(* Logix 5000 project; controller AMCI_3202_AOP_AOI_sample_RSLogix_V28 vendor 1 type 14 code 92 rev 28.11; software revision 28.00 *)

TASK MainTask (continuous, watchdog 500 ms) : MainProgram

MODULES
   Local : vendor 1 type 14 code 92 (ICP 0, rev 28.11)
      AMCI_3202 : vendor 10 type 100 code 32 (ICP 3, rev 1.1, Output RPI 5 ms)
      EN2TR : vendor 1 type 12 code 200 (ICP 2, Ethernet 192.168.0.5, rev 10.1)
END_MODULES

ADD_ON_INSTRUCTION AMCI_3202_AOP_Absolute_Move   (* revision 1.0, vendor AMCI, ExecuteEnableInFalse *)
VAR_INPUT
   axis_status_bits : INT; {required}
   channel_number : INT; {required}
   _0_normal_1_S_Curve_Acceleration : BOOL;
   _0_Triangular_1_Trapezoidal_S_Curve : BOOL;
   _0_Target_Position_1_Encoder_Move : BOOL;
   Target_Position : DINT; {required}
   Programmed_speed : DINT; {required}
   Acceleration : DINT; {required}
   Deceleration : DINT; {required}
END_VAR
VAR_IN_OUT
   AMCI_3202_output_data : AM:1756_3202:O:0; {required}
END_VAR
VAR_OUTPUT
   EN : BOOL; {access Read Only, visible}
   ER : BOOL; {access Read Only, visible}
END_VAR
VAR
   command_data_block : DINT[8]; {access None}
END_VAR

ROUTINE EnableInFalse   (* ladder *)
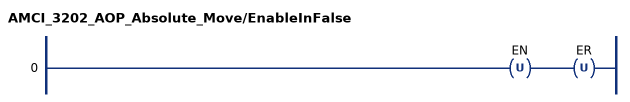
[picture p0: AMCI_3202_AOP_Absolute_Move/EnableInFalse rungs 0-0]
   0: OTU(EN)OTU(ER);
END_ROUTINE

ROUTINE Logic   (* ladder *)
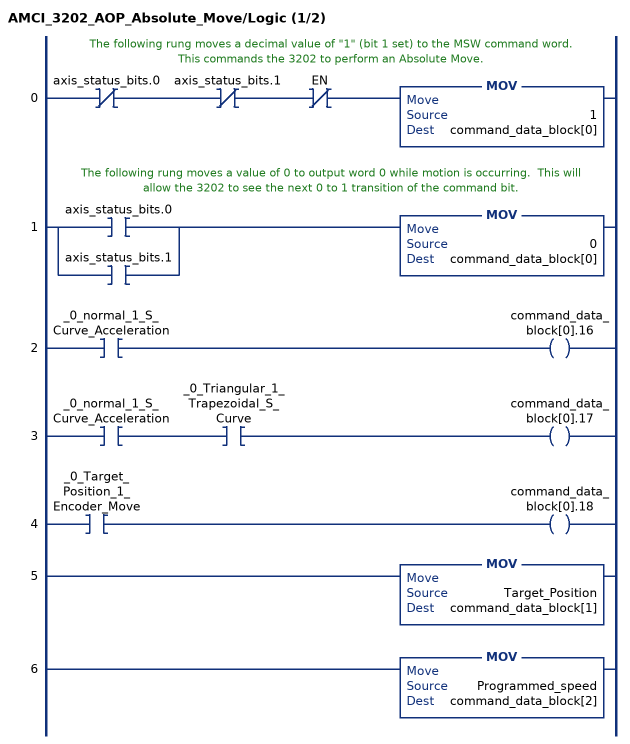
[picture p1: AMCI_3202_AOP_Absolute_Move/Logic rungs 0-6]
   // The following rung moves a decimal value of "1" (bit 1 set) to the MSW command word.  This commands the 3202 to perform an Absolute Move.
   0: XIO(axis_status_bits.0)XIO(axis_status_bits.1)XIO(EN)MOV(1,command_data_block[0]);
   // The following rung moves a value of 0 to output word 0 while motion is occurring.  This will allow the 3202 to see the next 0 to 1 transition of the command bit.
   1: [XIC(axis_status_bits.0) ,XIC(axis_status_bits.1) ]MOV(0,command_data_block[0]);
   2: XIC(_0_normal_1_S_Curve_Acceleration)OTE(command_data_block[0].16);
   3: XIC(_0_normal_1_S_Curve_Acceleration)XIC(_0_Triangular_1_Trapezoidal_S_Curve)OTE(command_data_block[0].17);
   4: XIC(_0_Target_Position_1_Encoder_Move)OTE(command_data_block[0].18);
   5: MOV(Target_Position,command_data_block[1]);
   6: MOV(Programmed_speed,command_data_block[2]);
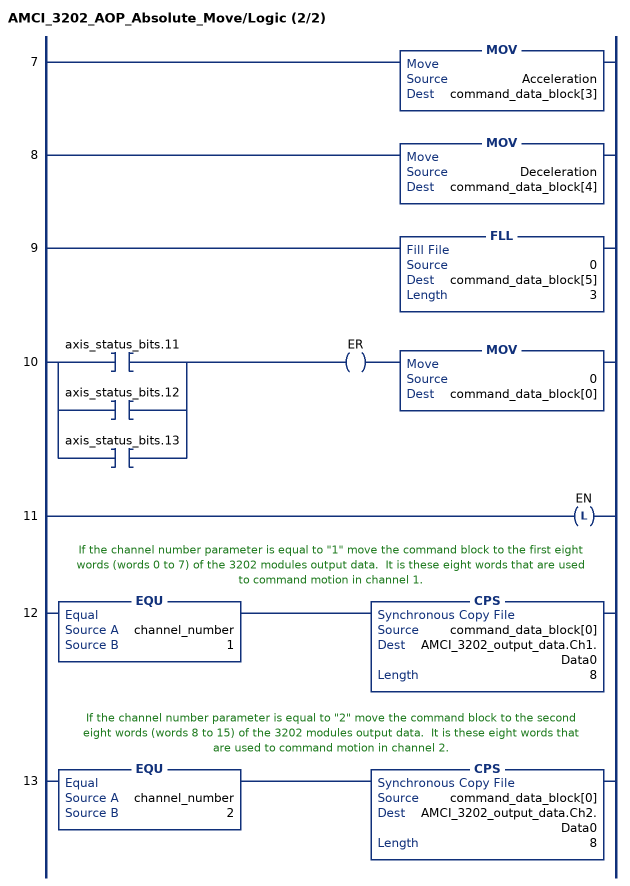
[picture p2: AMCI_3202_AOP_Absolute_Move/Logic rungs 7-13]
   7: MOV(Acceleration,command_data_block[3]);
   8: MOV(Deceleration,command_data_block[4]);
   9: FLL(0,command_data_block[5],3);
   10: [XIC(axis_status_bits.11) ,XIC(axis_status_bits.12) ,XIC(axis_status_bits.13) ]OTE(ER)MOV(0,command_data_block[0]);
   11: OTL(EN);
   // If the channel number parameter is equal to "1" move the command block to the first eight words (words 0 to 7) of the 3202 modules output data.  It is these eight words that are used to command motion in channel 1.
   12: EQU(channel_number,1)CPS(command_data_block[0],AMCI_3202_output_data.Ch1.Data0,8);
   // If the channel number parameter is equal to "2" move the command block to the second eight words (words 8 to 15) of the 3202 modules output data.  It is these eight words that are used to command motion in channel 2.
   13: EQU(channel_number,2)CPS(command_data_block[0],AMCI_3202_output_data.Ch2.Data0,8);
END_ROUTINE
END_ADD_ON_INSTRUCTION

ADD_ON_INSTRUCTION AMCI_3202_AOP_Configure   (* revision 1.0 *)
VAR_INPUT
   channel_number : INT; {required}
   capture_input : BOOL; {required}
   capture_input_active_state : BOOL; {required}
   external_input : BOOL; {required}
   external_input_active_state : BOOL; {required}
   home_input : BOOL; {required}
   home_input_active_state : BOOL; {required}
   Emergency_Stop : BOOL; {required}
   Emergency_Stop_active_state : BOOL; {required}
   CW_Limit : BOOL; {required}
   CW_Limit_actitve_state : BOOL; {required}
   CCW_Limit : BOOL; {required}
   CCW_Limit_active_state : BOOL; {required}
   Backplane_Home_Proximity_Enable : BOOL;
   Quad_Encoder : BOOL; {required}
   Diagnostic_Feedback : BOOL;
   _0_CW_CCW_1_step_direction : BOOL; {required}
   _0_enable_1_disable_channel : BOOL;
   Starting_Speed : DINT; {required}
   _0_limit_home_1_marker_pulse_home : BOOL;
END_VAR
VAR_IN_OUT
   AMCI_3202_output_data : AM:1756_3202:O:0; {required}
END_VAR
VAR
   command_data_block : DINT[8];
        [0].31   // Mode Bit 1=Configuraiton Mode 0=Command Mode
END_VAR

ROUTINE Logic   (* ladder *)
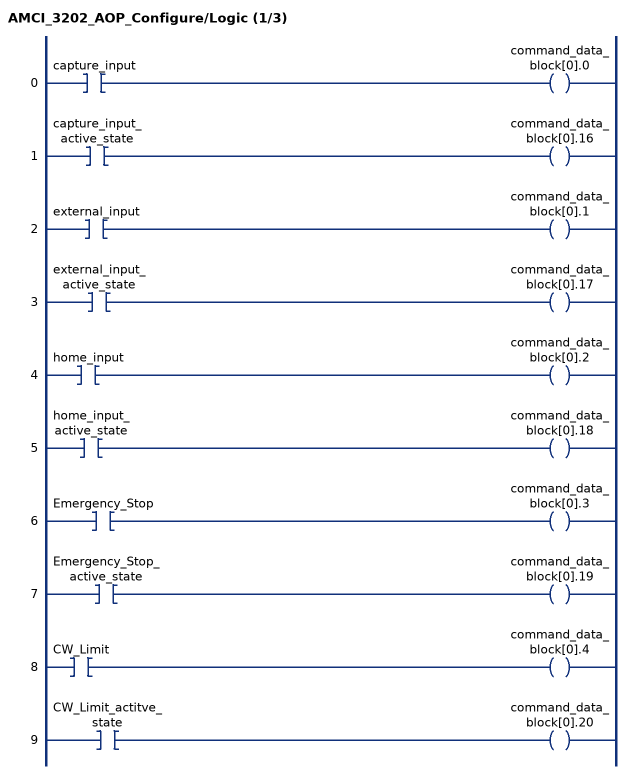
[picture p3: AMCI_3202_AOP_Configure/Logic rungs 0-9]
   0: XIC(capture_input)OTE(command_data_block[0].0);
   1: XIC(capture_input_active_state)OTE(command_data_block[0].16);
   2: XIC(external_input)OTE(command_data_block[0].1);
   3: XIC(external_input_active_state)OTE(command_data_block[0].17);
   4: XIC(home_input)OTE(command_data_block[0].2);
   5: XIC(home_input_active_state)OTE(command_data_block[0].18);
   6: XIC(Emergency_Stop)OTE(command_data_block[0].3);
   7: XIC(Emergency_Stop_active_state)OTE(command_data_block[0].19);
   8: XIC(CW_Limit)OTE(command_data_block[0].4);
   9: XIC(CW_Limit_actitve_state)OTE(command_data_block[0].20);
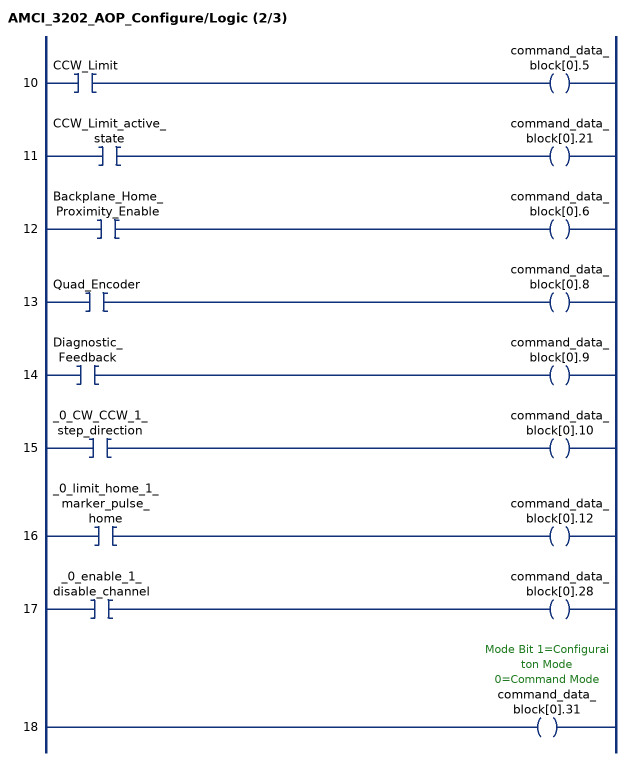
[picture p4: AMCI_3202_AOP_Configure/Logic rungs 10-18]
   10: XIC(CCW_Limit)OTE(command_data_block[0].5);
   11: XIC(CCW_Limit_active_state)OTE(command_data_block[0].21);
   12: XIC(Backplane_Home_Proximity_Enable)OTE(command_data_block[0].6);
   13: XIC(Quad_Encoder)OTE(command_data_block[0].8);
   14: XIC(Diagnostic_Feedback)OTE(command_data_block[0].9);
   15: XIC(_0_CW_CCW_1_step_direction)OTE(command_data_block[0].10);
   16: XIC(_0_limit_home_1_marker_pulse_home)OTE(command_data_block[0].12);
   17: XIC(_0_enable_1_disable_channel)OTE(command_data_block[0].28);
   18: OTE(command_data_block[0].31);
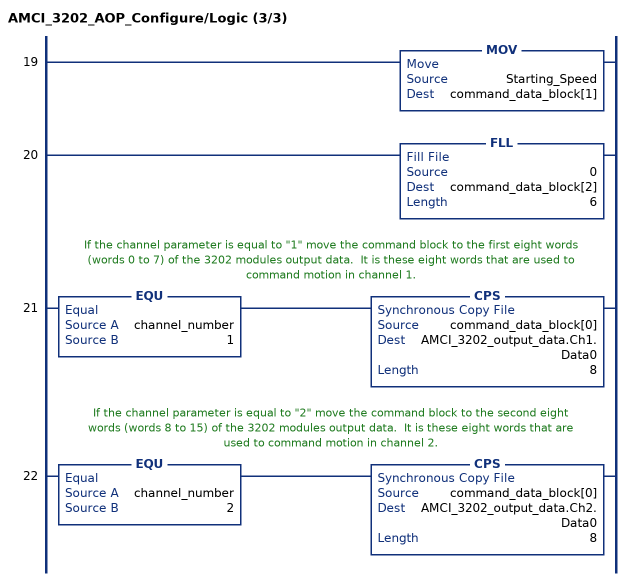
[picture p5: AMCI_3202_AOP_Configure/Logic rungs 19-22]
   19: MOV(Starting_Speed,command_data_block[1]);
   20: FLL(0,command_data_block[2],6);
   // If the channel parameter is equal to "1" move the command block to the first eight words (words 0 to 7) of the 3202 modules output data.  It is these eight words that are used to command motion in channel 1.
   21: EQU(channel_number,1)CPS(command_data_block[0],AMCI_3202_output_data.Ch1.Data0,8);
   // If the channel parameter is equal to "2" move the command block to the second eight words (words 8 to 15) of the 3202 modules output data.  It is these eight words that are used to command motion in channel 2.
   22: EQU(channel_number,2)CPS(command_data_block[0],AMCI_3202_output_data.Ch2.Data0,8);
END_ROUTINE
END_ADD_ON_INSTRUCTION

ADD_ON_INSTRUCTION AMCI_3202_AOP_Hold   (* revision 1.0, vendor AMCI, ExecuteEnableInFalse *)
VAR_INPUT
   channel_number : INT; {required}
END_VAR
VAR_IN_OUT
   AMCI_3202_output_data : AM:1756_3202:O:0; {required}
END_VAR
VAR
   command_data_block : DINT[8]; {access None}
END_VAR

ROUTINE EnableInFalse   (* ladder *)
END_ROUTINE

ROUTINE Logic   (* ladder *)
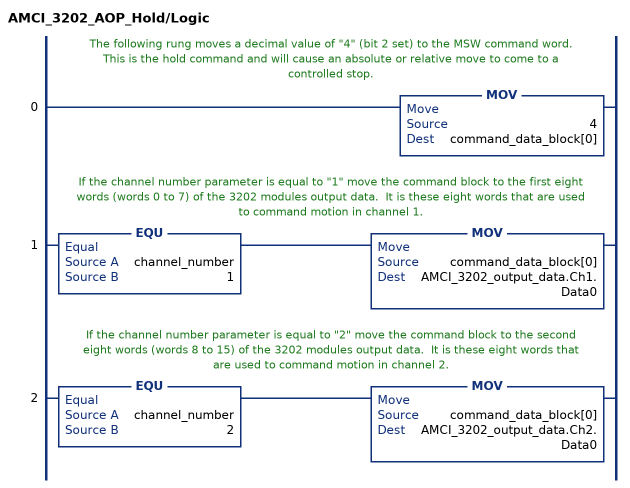
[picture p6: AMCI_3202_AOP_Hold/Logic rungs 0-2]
   // The following rung moves a decimal value of "4" (bit 2 set) to the MSW command word.  This is the hold command and will cause an absolute or relative move to come to a controlled stop.
   0: MOV(4,command_data_block[0]);
   // If the channel number parameter is equal to "1" move the command block to the first eight words (words 0 to 7) of the 3202 modules output data.  It is these eight words that are used to command motion in channel 1.
   1: EQU(channel_number,1)MOV(command_data_block[0],AMCI_3202_output_data.Ch1.Data0);
   // If the channel number parameter is equal to "2" move the command block to the second eight words (words 8 to 15) of the 3202 modules output data.  It is these eight words that are used to command motion in channel 2.
   2: EQU(channel_number,2)MOV(command_data_block[0],AMCI_3202_output_data.Ch2.Data0);
END_ROUTINE
END_ADD_ON_INSTRUCTION

ADD_ON_INSTRUCTION AMCI_3202_AOP_Home_CCW   (* revision 1.0, vendor AMCI, ExecuteEnableInFalse *)
VAR_INPUT
   axis_status_bits : INT; {required}
   channel_number : INT; {required}
   Programmed_speed : DINT; {required}
   Acceleration : DINT; {required}
   Deceleration : DINT; {required}
END_VAR
VAR_IN_OUT
   AMCI_3202_output_data : AM:1756_3202:O:0; {required}
END_VAR
VAR_OUTPUT
   EN : BOOL; {access Read Only, visible}
   ER : BOOL; {access Read Only, visible}
END_VAR
VAR
   command_data_block : DINT[8]; {access None}
END_VAR

ROUTINE EnableInFalse   (* ladder *)
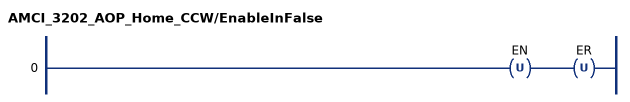
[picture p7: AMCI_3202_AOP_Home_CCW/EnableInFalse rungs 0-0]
   0: OTU(EN)OTU(ER);
END_ROUTINE

ROUTINE Logic   (* ladder *)
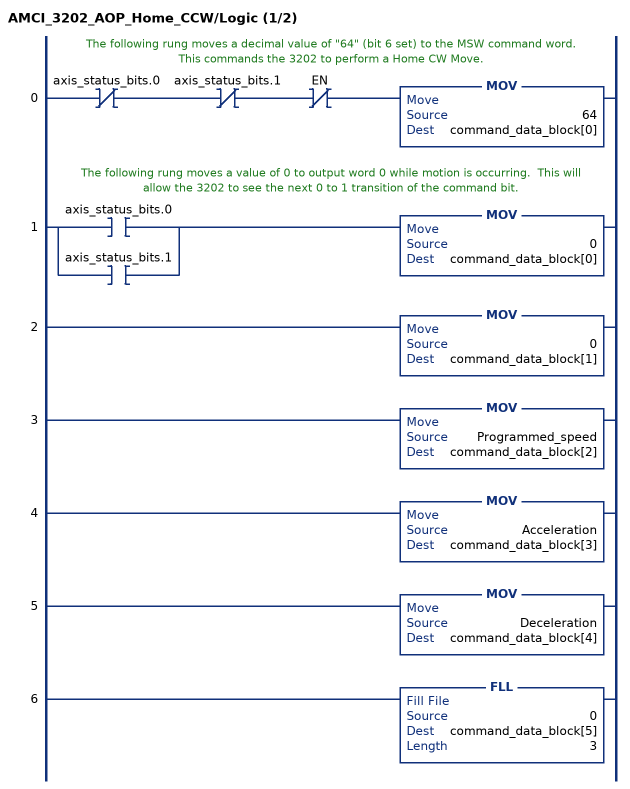
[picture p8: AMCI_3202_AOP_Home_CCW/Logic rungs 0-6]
   // The following rung moves a decimal value of "64" (bit 6 set) to the MSW command word.  This commands the 3202 to perform a Home CW Move.
   0: XIO(axis_status_bits.0)XIO(axis_status_bits.1)XIO(EN)MOV(64,command_data_block[0]);
   // The following rung moves a value of 0 to output word 0 while motion is occurring.  This will allow the 3202 to see the next 0 to 1 transition of the command bit.
   1: [XIC(axis_status_bits.0) ,XIC(axis_status_bits.1) ]MOV(0,command_data_block[0]);
   2: MOV(0,command_data_block[1]);
   3: MOV(Programmed_speed,command_data_block[2]);
   4: MOV(Acceleration,command_data_block[3]);
   5: MOV(Deceleration,command_data_block[4]);
   6: FLL(0,command_data_block[5],3);
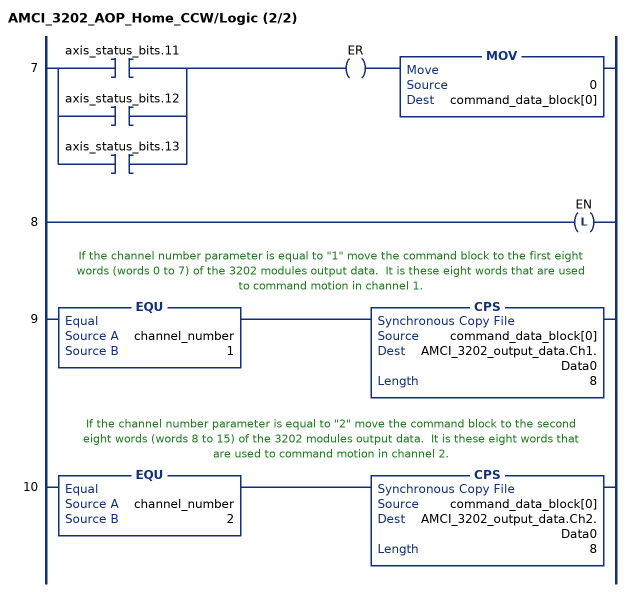
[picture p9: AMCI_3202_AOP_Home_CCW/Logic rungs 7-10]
   7: [XIC(axis_status_bits.11) ,XIC(axis_status_bits.12) ,XIC(axis_status_bits.13) ]OTE(ER)MOV(0,command_data_block[0]);
   8: OTL(EN);
   // If the channel number parameter is equal to "1" move the command block to the first eight words (words 0 to 7) of the 3202 modules output data.  It is these eight words that are used to command motion in channel 1.
   9: EQU(channel_number,1)CPS(command_data_block[0],AMCI_3202_output_data.Ch1.Data0,8);
   // If the channel number parameter is equal to "2" move the command block to the second eight words (words 8 to 15) of the 3202 modules output data.  It is these eight words that are used to command motion in channel 2.
   10: EQU(channel_number,2)CPS(command_data_block[0],AMCI_3202_output_data.Ch2.Data0,8);
END_ROUTINE
END_ADD_ON_INSTRUCTION

ADD_ON_INSTRUCTION AMCI_3202_AOP_Home_CW   (* revision 1.0, vendor AMCI, ExecuteEnableInFalse *)
VAR_INPUT
   axis_status_bits : INT; {required}
   channel_number : INT; {required}
   Programmed_speed : DINT; {required}
   Acceleration : DINT; {required}
   Deceleration : DINT; {required}
END_VAR
VAR_IN_OUT
   AMCI_3202_output_data : AM:1756_3202:O:0; {required}
END_VAR
VAR_OUTPUT
   EN : BOOL; {access Read Only, visible}
   ER : BOOL; {access Read Only, visible}
END_VAR
VAR
   command_data_block : DINT[8]; {access None}
END_VAR

ROUTINE EnableInFalse   (* ladder *)
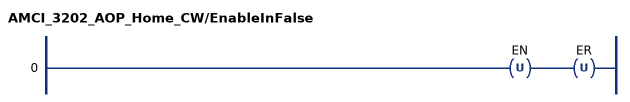
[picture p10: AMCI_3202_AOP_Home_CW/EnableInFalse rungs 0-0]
   0: OTU(EN)OTU(ER);
END_ROUTINE

ROUTINE Logic   (* ladder *)
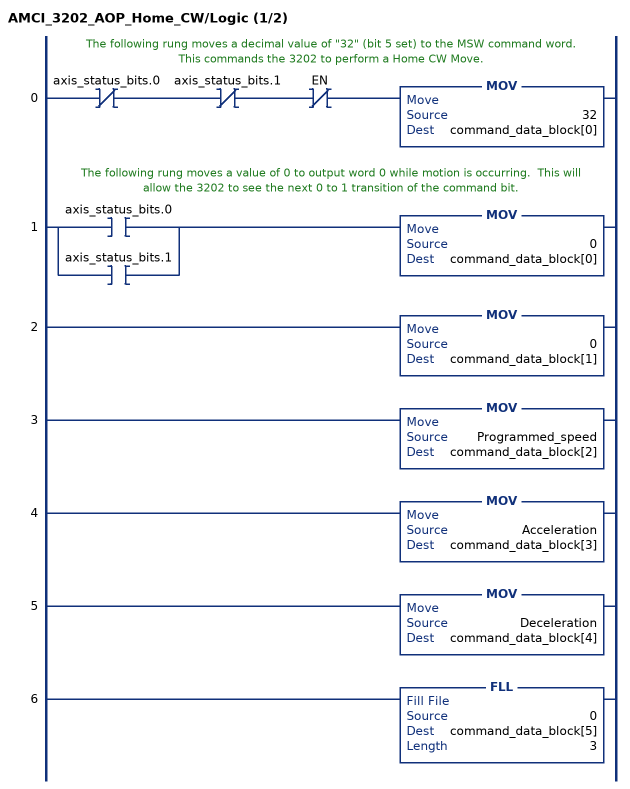
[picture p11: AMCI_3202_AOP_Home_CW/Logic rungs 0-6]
   // The following rung moves a decimal value of "32" (bit 5 set) to the MSW command word.  This commands the 3202 to perform a Home CW Move.
   0: XIO(axis_status_bits.0)XIO(axis_status_bits.1)XIO(EN)MOV(32,command_data_block[0]);
   // The following rung moves a value of 0 to output word 0 while motion is occurring.  This will allow the 3202 to see the next 0 to 1 transition of the command bit.
   1: [XIC(axis_status_bits.0) ,XIC(axis_status_bits.1) ]MOV(0,command_data_block[0]);
   2: MOV(0,command_data_block[1]);
   3: MOV(Programmed_speed,command_data_block[2]);
   4: MOV(Acceleration,command_data_block[3]);
   5: MOV(Deceleration,command_data_block[4]);
   6: FLL(0,command_data_block[5],3);
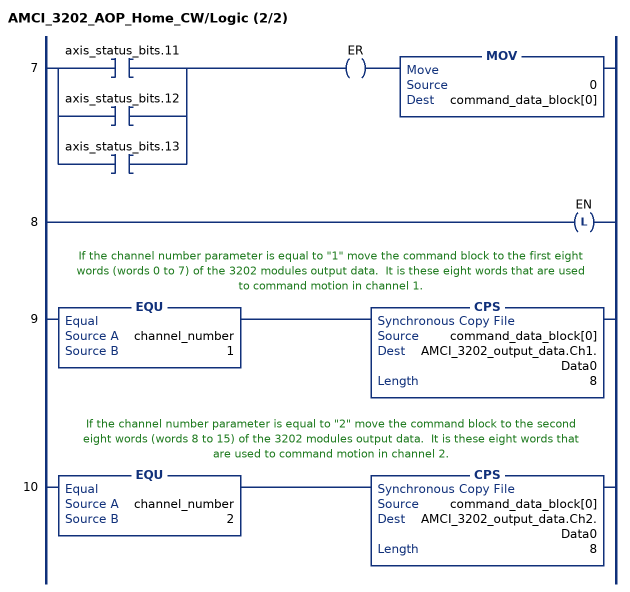
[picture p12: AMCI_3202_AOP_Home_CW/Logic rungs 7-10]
   7: [XIC(axis_status_bits.11) ,XIC(axis_status_bits.12) ,XIC(axis_status_bits.13) ]OTE(ER)MOV(0,command_data_block[0]);
   8: OTL(EN);
   // If the channel number parameter is equal to "1" move the command block to the first eight words (words 0 to 7) of the 3202 modules output data.  It is these eight words that are used to command motion in channel 1.
   9: EQU(channel_number,1)CPS(command_data_block[0],AMCI_3202_output_data.Ch1.Data0,8);
   // If the channel number parameter is equal to "2" move the command block to the second eight words (words 8 to 15) of the 3202 modules output data.  It is these eight words that are used to command motion in channel 2.
   10: EQU(channel_number,2)CPS(command_data_block[0],AMCI_3202_output_data.Ch2.Data0,8);
END_ROUTINE
END_ADD_ON_INSTRUCTION

ADD_ON_INSTRUCTION AMCI_3202_AOP_Immediate_Stop   (* revision 1.0, vendor AMCI, ExecuteEnableInFalse *)
VAR_INPUT
   channel_number : INT; {required}
END_VAR
VAR_IN_OUT
   AMCI_3202_output_data : AM:1756_3202:O:0; {required}
END_VAR
VAR
   command_data_block : DINT[8]; {access None}
END_VAR

ROUTINE EnableInFalse   (* ladder *)
END_ROUTINE

ROUTINE Logic   (* ladder *)
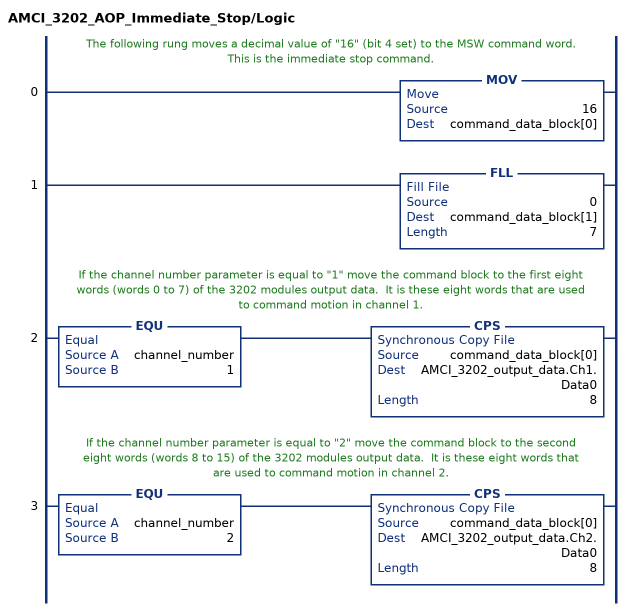
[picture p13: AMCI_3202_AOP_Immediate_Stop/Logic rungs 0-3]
   // The following rung moves a decimal value of "16" (bit 4 set) to the MSW command word.  This is the immediate stop command.
   0: MOV(16,command_data_block[0]);
   1: FLL(0,command_data_block[1],7);
   // If the channel number parameter is equal to "1" move the command block to the first eight words (words 0 to 7) of the 3202 modules output data.  It is these eight words that are used to command motion in channel 1.
   2: EQU(channel_number,1)CPS(command_data_block[0],AMCI_3202_output_data.Ch1.Data0,8);
   // If the channel number parameter is equal to "2" move the command block to the second eight words (words 8 to 15) of the 3202 modules output data.  It is these eight words that are used to command motion in channel 2.
   3: EQU(channel_number,2)CPS(command_data_block[0],AMCI_3202_output_data.Ch2.Data0,8);
END_ROUTINE
END_ADD_ON_INSTRUCTION

ADD_ON_INSTRUCTION AMCI_3202_AOP_Manual_Move_CCW   (* revision 1.0, vendor AMCI, ExecuteEnableInFalse *)
VAR_INPUT
   axis_status_bits : INT; {required}
   channel_number : INT; {required}
   _0_normal_1_S_Curve_Acceleration : BOOL;
   _0_Triangular_1_Trapezoidal_S_Curve : BOOL;
   Programmed_speed : DINT; {required}
   Acceleration : DINT; {required}
   Deceleration : DINT; {required}
END_VAR
VAR_IN_OUT
   AMCI_3202_output_data : AM:1756_3202:O:0; {required}
END_VAR
VAR_OUTPUT
   EN : BOOL; {access Read Only, visible}
   Manual_Move_CCW_occurring : BOOL; {access Read Only, visible}
   ER : BOOL; {access Read Only, visible}
END_VAR
VAR
   command_data_block : DINT[8]; {access None}
END_VAR

ROUTINE EnableInFalse   (* ladder *)
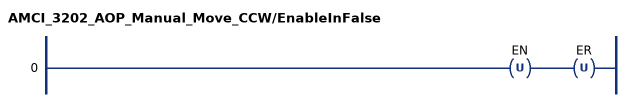
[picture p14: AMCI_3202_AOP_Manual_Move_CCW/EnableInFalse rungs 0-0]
   0: OTU(EN)OTU(ER);
END_ROUTINE

ROUTINE Logic   (* ladder *)
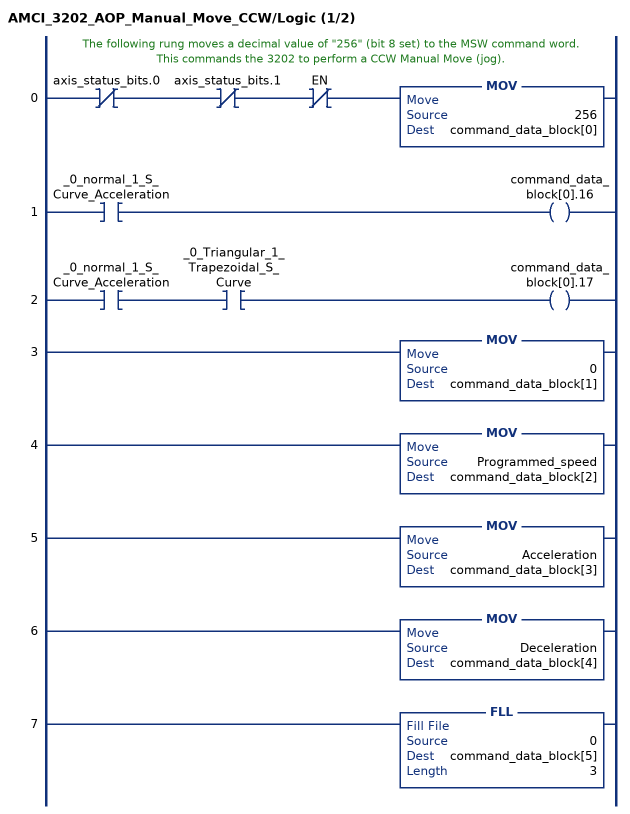
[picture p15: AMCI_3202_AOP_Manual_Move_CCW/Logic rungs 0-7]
   // The following rung moves a decimal value of "256" (bit 8 set) to the MSW command word.  This commands the 3202 to perform a CCW Manual Move (jog).
   0: XIO(axis_status_bits.0)XIO(axis_status_bits.1)XIO(EN)MOV(256,command_data_block[0]);
   1: XIC(_0_normal_1_S_Curve_Acceleration)OTE(command_data_block[0].16);
   2: XIC(_0_normal_1_S_Curve_Acceleration)XIC(_0_Triangular_1_Trapezoidal_S_Curve)OTE(command_data_block[0].17);
   3: MOV(0,command_data_block[1]);
   4: MOV(Programmed_speed,command_data_block[2]);
   5: MOV(Acceleration,command_data_block[3]);
   6: MOV(Deceleration,command_data_block[4]);
   7: FLL(0,command_data_block[5],3);
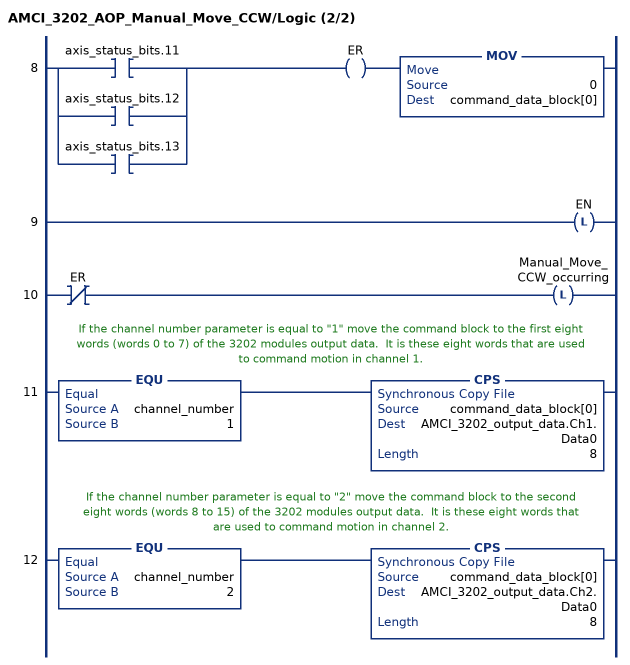
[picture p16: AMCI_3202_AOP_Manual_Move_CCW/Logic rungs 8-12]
   8: [XIC(axis_status_bits.11) ,XIC(axis_status_bits.12) ,XIC(axis_status_bits.13) ]OTE(ER)MOV(0,command_data_block[0]);
   9: OTL(EN);
   10: XIO(ER)OTL(Manual_Move_CCW_occurring);
   // If the channel number parameter is equal to "1" move the command block to the first eight words (words 0 to 7) of the 3202 modules output data.  It is these eight words that are used to command motion in channel 1.
   11: EQU(channel_number,1)CPS(command_data_block[0],AMCI_3202_output_data.Ch1.Data0,8);
   // If the channel number parameter is equal to "2" move the command block to the second eight words (words 8 to 15) of the 3202 modules output data.  It is these eight words that are used to command motion in channel 2.
   12: EQU(channel_number,2)CPS(command_data_block[0],AMCI_3202_output_data.Ch2.Data0,8);
END_ROUTINE
END_ADD_ON_INSTRUCTION

ADD_ON_INSTRUCTION AMCI_3202_AOP_Manual_Move_CW   (* revision 1.0, vendor AMCI, ExecuteEnableInFalse *)
VAR_INPUT
   axis_status_bits : INT; {required}
   channel_number : INT; {required}
   _0_normal_1_S_Curve_Acceleration : BOOL;
   _0_Triangular_1_Trapezoidal_S_Curve : BOOL;
   Programmed_speed : DINT; {required}
   Acceleration : DINT; {required}
   Deceleration : DINT; {required}
END_VAR
VAR_IN_OUT
   AMCI_3202_output_data : AM:1756_3202:O:0; {required}
END_VAR
VAR_OUTPUT
   EN : BOOL; {access Read Only, visible}
   Manual_Move_CW_occurring : BOOL; {access Read Only, visible}
   ER : BOOL; {access Read Only, visible}
END_VAR
VAR
   command_data_block : DINT[8]; {access None}
END_VAR

ROUTINE EnableInFalse   (* ladder *)
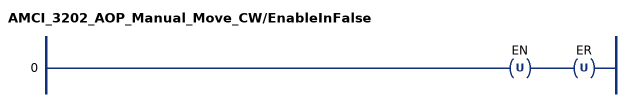
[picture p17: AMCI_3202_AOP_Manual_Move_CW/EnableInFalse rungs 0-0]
   0: OTU(EN)OTU(ER);
END_ROUTINE
